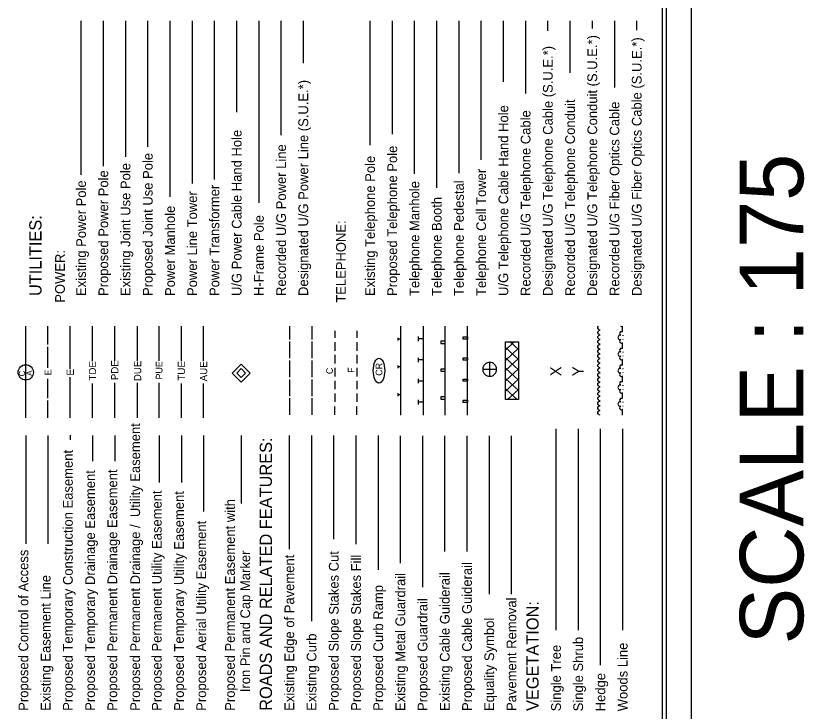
# Model space of a CAD drawing. Extents: x 2026893 to 2039781, y 729195 to 739590.
# Drawn here: x 2037298 to 2039781, y 735661 to 737852 of the extents above; entities that cross this region are included whole.
import ezdxf

# ---------------------------------------------------------------- set-up
doc = ezdxf.new("R2010")
doc.units = 0
for name, color, linetype in [('Prop Easement Permanent Drainage Utility', 7, 'Continuous'), ('Prop ROW Permanent Easement CELL', 7, 'Continuous'), ('Prop WCC CELL', 7, 'Continuous'), ('Scratch_Level_3', 7, 'Continuous'), ('Sheet Cutting Line CELL', 7, 'Continuous'), ('Sheet Plot Border Inside CELL', 7, 'Continuous'), ('Sheet Plot Border Outside CELL', 7, 'Continuous'), ('Sheet Symbology CELL', 7, 'Continuous')]:
    doc.layers.add(name, color=color, linetype=linetype)

msp = doc.modelspace()

# ---------------------------------------------------------------- linework, layer by layer
at = {"layer": 'Prop Easement Permanent Drainage Utility'}
for p, q in [((2037681.1, 736764.7), (2037681.1, 736873.9)), ((2037681.1, 736585.2), (2037681.1, 736694.7))]:
    msp.add_line(p, q, dxfattribs=at)
at = {"layer": 'Prop ROW Permanent Easement CELL'}
msp.add_line((2038007.5, 736725.7), (2038007.5, 736725.7), dxfattribs=at)
for points in [[(2037979.3, 736725.7), (2038007.5, 736753.9), (2038035.6, 736725.7), (2038007.5, 736697.5)], [(2037993.4, 736725.7), (2038007.5, 736739.8), (2038021.5, 736725.7), (2038007.5, 736711.6)]]:
    msp.add_lwpolyline(points, close=True, dxfattribs=at)
at = {"layer": 'Prop WCC CELL'}
msp.add_ellipse((2038441.5, 736733.8), major_axis=(0, 39.2), ratio=0.462467, dxfattribs=at)
at = {"layer": 'Sheet Cutting Line CELL'}
msp.add_line((2039425.3, 733695.9), (2039425.3, 739589.9), dxfattribs=at)
at = {"layer": 'Sheet Plot Border Inside CELL'}
msp.add_lwpolyline([(2039346.7, 733741.4), (2039346.7, 739574.2), (2035653.9, 739574.2), (2035653.9, 733741.4)], close=True, dxfattribs=at)
at = {"layer": 'Sheet Plot Border Outside CELL'}
msp.add_lwpolyline([(2039425.3, 733695.9), (2039425.3, 739589.9), (2035575.3, 739589.9), (2035575.3, 733695.9)], close=True, dxfattribs=at)
at = {"layer": 'Sheet Symbology CELL'}
for p, q in [((2037502.7, 737835.7), (2037502.7, 737350.3)), ((2037572.7, 737835.7), (2037572.7, 737377.5)), ((2037642.7, 737835.7), (2037642.7, 737406.9)), ((2037712.7, 737835.7), (2037712.7, 737438.4)), ((2037782.7, 737835.7), (2037782.7, 737281)), ((2037852.7, 737835.7), (2037852.7, 737323)), ((2037922.7, 737835.7), (2037922.7, 737335.6)), ((2037992.7, 737835.7), (2037992.7, 737547.6)), ((2038062.7, 737835.7), (2038062.7, 737262.1)), ((2038132.7, 737835.7), (2038132.7, 737475.4)), ((2038202.7, 737835.7), (2038202.7, 737702)), ((2038412.7, 737835.7), (2038412.7, 737444.1)), ((2038482.7, 737835.7), (2038482.7, 737478.5)), ((2038552.7, 737835.7), (2038552.7, 737353.2)), ((2038622.7, 737835.7), (2038622.7, 737309)), ((2038692.7, 737835.7), (2038692.7, 737355.7)), ((2038762.7, 737835.7), (2038762.7, 737397.5)), ((2038832.7, 737835.7), (2038832.7, 737643.1)), ((2038902.7, 737835.7), (2038902.7, 737606.3)), ((2038972.7, 737835.7), (2038972.7, 737803.8)), ((2039042.7, 737835.7), (2039042.7, 737671.5)), ((2039112.7, 737835.7), (2039112.7, 737811)), ((2039182.7, 737835.7), (2039182.7, 737625.7)), ((2039252.7, 737835.7), (2039252.7, 737805.8)), ((2037329, 736585.2), (2037329, 736873.9)), ((2037399, 736815.4), (2037399, 736873.9)), ((2037469, 736856.8), (2037469, 736873.9)), ((2037469, 736738.7), (2037469, 736856.8)), ((2037539, 736859.4), (2037539, 736873.9)), ((2037539, 736763.2), (2037539, 736859.4)), ((2037609, 736861), (2037609, 736873.9)), ((2037609, 736764.7), (2037609, 736861)), ((2037749.1, 736861.1), (2037749.1, 736873.9)), ((2037749.1, 736764.9), (2037749.1, 736861.1)), ((2037819.1, 736859.4), (2037819.1, 736873.9)), ((2037819.1, 736763.2), (2037819.1, 736859.4)), ((2037889.1, 736859.4), (2037889.1, 736873.9)), ((2037889.1, 736763.2), (2037889.1, 736859.4)), ((2038160.5, 736831.9), (2038160.5, 736873.9)), ((2038230.5, 736831.9), (2038230.5, 736873.9)), ((2038302.2, 736859.4), (2038302.2, 736837)), ((2038372.2, 736859.4), (2038372.2, 736837)), ((2038510.1, 736593.4), (2038510.1, 736873.4)), ((2038580.1, 736873.4), (2038580.1, 736593.4)), ((2038650.1, 736593.4), (2038650.1, 736873.4)), ((2038720.1, 736593.4), (2038720.1, 736873.4)), ((2039131.2, 736870.4), (2039132.9, 736873.2)), ((2039131.2, 736867.1), (2039131.2, 736870.4)), ((2039132.7, 736864.3), (2039131.2, 736867.1)), ((2039131.2, 736855.5), (2039132.9, 736858.3)), ((2039131.2, 736852.2), (2039131.2, 736855.5)), ((2039135, 736862.2), (2039132.7, 736864.3)), ((2039132.9, 736873.2), (2039133.1, 736873.4)), ((2039132.9, 736858.3), (2039135.2, 736860.3)), ((2039138.3, 736861.1), (2039135, 736862.2)), ((2039135.2, 736860.3), (2039138.2, 736861)), ((2039208.3, 736855.9), (2039208.3, 736873.4)), ((2038501.4, 736828.4), (2038501.4, 736837.1)), ((2038510.1, 736832.7), (2038501.4, 736832.7)), ((2038566.3, 736826.9), (2038566.3, 736840.9)), ((2038580.1, 736833.9), (2038566.3, 736833.9)), ((2039132.7, 736849.4), (2039131.2, 736852.2)), ((2039131.2, 736840.7), (2039132.9, 736843.5)), ((2039131.2, 736837.3), (2039131.2, 736840.7)), ((2039132.7, 736834.5), (2039131.2, 736837.3)), ((2039135, 736847.3), (2039132.7, 736849.4)), ((2039135, 736832.4), (2039132.7, 736834.5)), ((2039132.9, 736843.5), (2039135.2, 736845.4)), ((2039132.9, 736828.6), (2039135.2, 736830.5)), ((2039138.3, 736846.3), (2039135, 736847.3)), ((2039138.3, 736831.4), (2039135, 736832.4)), ((2039135.2, 736845.4), (2039138.2, 736846.1)), ((2039135.2, 736830.5), (2039138.2, 736831.2)), ((2039210.1, 736843.5), (2039210.1, 736845.2)), ((2039210.1, 736831.2), (2039210.1, 736833)), ((2037399, 736742.7), (2037399, 736808.4)), ((2038160.5, 736772.4), (2038160.5, 736824.9)), ((2038230.5, 736772.4), (2038230.5, 736824.9)), ((2038302.2, 736823.4), (2038302.2, 736795.9)), ((2038372.2, 736823.4), (2038372.2, 736795.9)), ((2038839.6, 736642.2), (2038839.6, 736824.6)), ((2038839.6, 736824.6), (2038880.5, 736824.6)), ((2038867.4, 736824.6), (2038839.6, 736798.5)), ((2038880.5, 736768.2), (2038839.6, 736806.5)), ((2038880.5, 736804.6), (2038839.6, 736765.9)), ((2038880.5, 736800.6), (2038855, 736824.6)), ((2038880.5, 736824.6), (2038880.5, 736642.2)), ((2039131.2, 736825.8), (2039132.9, 736828.6)), ((2039131.2, 736822.5), (2039131.2, 736825.8)), ((2039132.7, 736819.7), (2039131.2, 736822.5)), ((2039131.2, 736810.9), (2039132.9, 736813.7)), ((2039131.2, 736807.6), (2039131.2, 736810.9)), ((2039132.7, 736804.8), (2039131.2, 736807.6)), ((2039135, 736817.6), (2039132.7, 736819.7)), ((2039135, 736802.7), (2039132.7, 736804.8)), ((2039132.9, 736813.7), (2039135.2, 736815.6)), ((2039138.3, 736816.5), (2039135, 736817.6)), ((2039135.2, 736815.6), (2039138.2, 736816.3)), ((2039208.3, 736803.4), (2039208.3, 736820.9)), ((2038302.2, 736782.9), (2038302.2, 736755.8)), ((2038372.2, 736782.9), (2038372.2, 736755.8)), ((2039131.2, 736796), (2039132.9, 736798.8)), ((2039131.2, 736792.7), (2039131.2, 736796)), ((2039132.7, 736789.9), (2039131.2, 736792.7)), ((2039131.2, 736781.2), (2039132.9, 736784)), ((2039131.2, 736777.8), (2039131.2, 736781.2)), ((2039135, 736787.8), (2039132.7, 736789.9)), ((2039132.9, 736798.8), (2039135.2, 736800.8)), ((2039132.9, 736784), (2039135.2, 736785.9)), ((2039138.3, 736801.6), (2039135, 736802.7)), ((2039138.3, 736786.8), (2039135, 736787.8)), ((2039135.2, 736800.8), (2039138.2, 736801.5)), ((2039135.2, 736785.9), (2039138.2, 736786.6)), ((2039210.1, 736791), (2039210.1, 736792.7)), ((2039210.1, 736778.7), (2039210.1, 736780.5)), ((2038160.5, 736712.9), (2038160.5, 736765.4)), ((2038230.5, 736712.9), (2038230.5, 736765.4)), ((2038566.3, 736760.4), (2038566.3, 736774.4)), ((2038580.1, 736767.4), (2038566.3, 736767.4)), ((2038790.1, 736737.7), (2038790.1, 736759.5)), ((2038880.5, 736735.7), (2038839.6, 736774.2)), ((2038880.5, 736772.1), (2038839.6, 736733.6)), ((2039132.7, 736775), (2039131.2, 736777.8)), ((2039131.2, 736766.3), (2039132.9, 736769.1)), ((2039131.2, 736763), (2039131.2, 736766.3)), ((2039132.7, 736760.2), (2039131.2, 736763)), ((2039135, 736772.9), (2039132.7, 736775)), ((2039135, 736758.1), (2039132.7, 736760.2)), ((2039132.9, 736769.1), (2039135.2, 736771)), ((2039132.9, 736754.2), (2039135.2, 736756.1)), ((2039138.3, 736771.9), (2039135, 736772.9)), ((2039138.3, 736757), (2039135, 736758.1)), ((2039135.2, 736771), (2039138.2, 736771.7)), ((2039135.2, 736756.1), (2039138.2, 736756.8)), ((2039208.3, 736750.9), (2039208.3, 736768.4)), ((2038302.2, 736742.9), (2038302.2, 736715.6)), ((2038372.2, 736742.9), (2038372.2, 736715.6)), ((2038501.4, 736740.9), (2038501.4, 736749.6)), ((2038510.1, 736745.2), (2038501.4, 736745.2)), ((2038768.3, 736737.7), (2038790.1, 736737.7)), ((2038790.1, 736715.8), (2038790.1, 736737.7)), ((2038790.1, 736737.7), (2038812, 736737.7)), ((2038880.5, 736703.1), (2038839.6, 736741.8)), ((2038880.5, 736739.5), (2038839.6, 736701.2)), ((2039131.2, 736751.4), (2039132.9, 736754.2)), ((2039131.2, 736748.1), (2039131.2, 736751.4)), ((2039132.7, 736745.3), (2039131.2, 736748.1)), ((2039131.2, 736736.5), (2039132.9, 736739.3)), ((2039131.2, 736733.2), (2039131.2, 736736.5)), ((2039132.7, 736730.4), (2039131.2, 736733.2)), ((2039135, 736743.2), (2039132.7, 736745.3)), ((2039135, 736728.3), (2039132.7, 736730.4)), ((2039132.9, 736739.3), (2039135.2, 736741.3)), ((2039138.3, 736742.1), (2039135, 736743.2)), ((2039135.2, 736741.3), (2039138.2, 736742)), ((2039210.1, 736738.5), (2039210.1, 736740.2)), ((2037399, 736646.5), (2037399, 736707.7)), ((2037469, 736594.3), (2037469, 736712.5)), ((2038160.5, 736653.4), (2038160.5, 736705.9)), ((2038230.5, 736653.4), (2038230.5, 736705.9)), ((2038566.3, 736693.9), (2038566.3, 736707.9)), ((2038880.5, 736670.7), (2038839.6, 736709.2)), ((2038880.5, 736707.1), (2038839.6, 736668.6)), ((2039131.2, 736721.7), (2039132.9, 736724.5)), ((2039131.2, 736718.3), (2039131.2, 736721.7)), ((2039132.7, 736715.5), (2039131.2, 736718.3)), ((2039131.2, 736706.8), (2039132.9, 736709.6)), ((2039131.2, 736703.5), (2039131.2, 736706.8)), ((2039135, 736713.4), (2039132.7, 736715.5)), ((2039132.9, 736724.5), (2039135.2, 736726.4)), ((2039132.9, 736709.6), (2039135.2, 736711.5)), ((2039138.3, 736727.3), (2039135, 736728.3)), ((2039138.3, 736712.4), (2039135, 736713.4)), ((2039135.2, 736726.4), (2039138.2, 736727.1)), ((2039135.2, 736711.5), (2039138.2, 736712.2)), ((2039208.3, 736698.4), (2039208.3, 736715.9)), ((2039210.1, 736726.2), (2039210.1, 736728)), ((2037539, 736596.9), (2037539, 736693.2)), ((2037609, 736598.5), (2037609, 736694.7)), ((2037749.1, 736598.6), (2037749.1, 736694.9)), ((2037819.1, 736596.9), (2037819.1, 736693.2)), ((2037889.1, 736596.9), (2037889.1, 736693.2)), ((2038302.2, 736701.7), (2038302.2, 736675.1)), ((2038372.2, 736701.7), (2038372.2, 736675.1)), ((2038580.1, 736700.9), (2038566.3, 736700.9)), ((2039132.7, 736700.7), (2039131.2, 736703.5)), ((2039131.2, 736691.9), (2039132.9, 736694.7)), ((2039131.2, 736688.6), (2039131.2, 736691.9)), ((2039132.7, 736685.8), (2039131.2, 736688.6)), ((2039135, 736698.6), (2039132.7, 736700.7)), ((2039135, 736683.7), (2039132.7, 736685.8)), ((2039132.9, 736694.7), (2039135.2, 736696.6)), ((2039132.9, 736679.8), (2039135.2, 736681.8)), ((2039138.3, 736697.5), (2039135, 736698.6)), ((2039138.3, 736682.6), (2039135, 736683.7)), ((2039135.2, 736696.6), (2039138.2, 736697.3)), ((2039135.2, 736681.8), (2039138.2, 736682.5)), ((2039210.1, 736686), (2039210.1, 736687.7)), ((2038302.2, 736661.5), (2038302.2, 736635.1)), ((2038372.2, 736661.5), (2038372.2, 736635.1)), ((2038501.4, 736653.4), (2038501.4, 736662.1)), ((2038510.1, 736657.7), (2038501.4, 736657.7)), ((2038876.5, 736642.2), (2038839.6, 736676.7)), ((2038880.5, 736674.6), (2038845.9, 736642.2)), ((2039131.2, 736677), (2039132.9, 736679.8)), ((2039131.2, 736673.7), (2039131.2, 736677)), ((2039132.7, 736670.9), (2039131.2, 736673.7)), ((2039131.2, 736662.2), (2039132.9, 736665)), ((2039131.2, 736658.8), (2039131.2, 736662.2)), ((2039132.7, 736656), (2039131.2, 736658.8)), ((2039135, 736668.8), (2039132.7, 736670.9)), ((2039135, 736653.9), (2039132.7, 736656)), ((2039132.9, 736665), (2039135.2, 736666.9)), ((2039138.3, 736667.8), (2039135, 736668.8)), ((2039135.2, 736666.9), (2039138.2, 736667.6)), ((2039208.3, 736645.9), (2039208.3, 736663.4)), ((2039210.1, 736673.7), (2039210.1, 736675.5)), ((2037399, 736585.2), (2037399, 736639.5)), ((2038160.5, 736593.9), (2038160.5, 736646.4)), ((2038230.5, 736593.9), (2038230.5, 736646.4)), ((2038566.3, 736627.4), (2038566.3, 736641.4)), ((2038580.1, 736634.4), (2038566.3, 736634.4)), ((2038841.7, 736642.2), (2038839.6, 736644.1)), ((2038880.5, 736642.2), (2038839.6, 736642.2)), ((2039131.2, 736647.3), (2039132.9, 736650.1)), ((2039131.2, 736644), (2039131.2, 736647.3)), ((2039132.7, 736641.2), (2039131.2, 736644)), ((2039131.2, 736632.4), (2039132.9, 736635.2)), ((2039131.2, 736629.1), (2039131.2, 736632.4)), ((2039135, 736639.1), (2039132.7, 736641.2)), ((2039132.9, 736650.1), (2039135.2, 736652)), ((2039132.9, 736635.2), (2039135.2, 736637.1)), ((2039138.3, 736652.9), (2039135, 736653.9)), ((2039138.3, 736638), (2039135, 736639.1)), ((2039135.2, 736652), (2039138.2, 736652.7)), ((2039135.2, 736637.1), (2039138.2, 736637.8)), ((2039210.1, 736633.5), (2039210.1, 736635.2)), ((2038302.2, 736593.9), (2038302.2, 736620.5)), ((2038372.2, 736593.9), (2038372.2, 736620.5)), ((2039132.7, 736626.3), (2039131.2, 736629.1)), ((2039131.2, 736617.5), (2039132.9, 736620.3)), ((2039131.2, 736614.2), (2039131.2, 736617.5)), ((2039132.7, 736611.4), (2039131.2, 736614.2)), ((2039131.2, 736602.7), (2039132.9, 736605.5)), ((2039135, 736624.2), (2039132.7, 736626.3)), ((2039135, 736609.3), (2039132.7, 736611.4)), ((2039132.9, 736620.3), (2039135.2, 736622.3)), ((2039132.9, 736605.5), (2039135.2, 736607.4)), ((2039138.3, 736623.1), (2039135, 736624.2)), ((2039138.3, 736608.3), (2039135, 736609.3)), ((2039135.2, 736622.3), (2039138.2, 736623)), ((2039135.2, 736607.4), (2039138.2, 736608.1)), ((2039208.3, 736593.4), (2039208.3, 736610.9)), ((2039210.1, 736621.2), (2039210.1, 736623)), ((2037469, 736585.2), (2037469, 736594.3)), ((2037539, 736585.2), (2037539, 736596.9)), ((2037609, 736585.2), (2037609, 736598.5)), ((2037749.1, 736585.2), (2037749.1, 736598.6)), ((2037819.1, 736585.2), (2037819.1, 736596.9)), ((2037889.1, 736585.2), (2037889.1, 736596.9)), ((2039131.2, 736599.3), (2039131.2, 736602.7)), ((2039132.7, 736596.5), (2039131.2, 736599.3)), ((2039135, 736594.4), (2039132.7, 736596.5)), ((2039138.3, 736593.4), (2039135, 736594.4)), ((2038998.3, 736550), (2038998.3, 735916.1)), ((2039068.3, 736550), (2039068.3, 735916.1)), ((2039138.3, 736550), (2039138.3, 735805.6)), ((2039208.3, 736550), (2039208.3, 735916.1)), ((2037329, 736529.1), (2037329, 736187.7)), ((2037399, 736529.1), (2037399, 736187.7)), ((2037469, 736530.4), (2037469, 736515.8)), ((2037539, 736529.1), (2037539, 736448.1)), ((2037609, 736529.1), (2037609, 736448.1)), ((2037749.1, 736529.1), (2037749.1, 736381.6)), ((2037819.1, 736529.1), (2037819.1, 736381.6)), ((2037889.1, 736529.1), (2037889.1, 736289.5)), ((2038007.5, 736529.1), (2038007.5, 736315.5)), ((2038158.5, 736529.1), (2038158.5, 736170.9)), ((2038228.5, 736529.1), (2038228.5, 735944.1)), ((2038298.5, 736529.1), (2038298.5, 736202.9)), ((2038368.5, 736529.1), (2038368.5, 736187)), ((2038438.5, 736529.1), (2038438.5, 736105.8)), ((2038508.1, 736528.5), (2038508.1, 736126.6)), ((2038578.1, 736528.5), (2038578.1, 736051.7)), ((2038648.1, 736528.5), (2038648.1, 736163.5)), ((2038718.1, 736528.5), (2038718.1, 736163.5)), ((2038788.1, 736528.5), (2038788.1, 736029.3)), ((2038858.1, 736528.5), (2038858.1, 736029.3))]:
    msp.add_line(p, q, dxfattribs=at)
for points in [[(2035662.8, 739530.4), (2035662.8, 734280.4), (2039334.3, 734280.4), (2039334.3, 739530.4)], [(2038706.1, 736833), (2038706.1, 736840), (2038720.1, 736840), (2038720.1, 736833)], [(2038650.1, 736819), (2038650.1, 736826), (2038636.1, 736826), (2038636.1, 736819)], [(2038706.1, 736766.5), (2038706.1, 736773.5), (2038720.1, 736773.5), (2038720.1, 736766.5)], [(2038650.1, 736731.5), (2038650.1, 736738.5), (2038636.1, 736738.5), (2038636.1, 736731.5)], [(2038706.1, 736700), (2038706.1, 736707), (2038720.1, 736707), (2038720.1, 736700)], [(2038650.1, 736644), (2038650.1, 736651), (2038636.1, 736651), (2038636.1, 736644)], [(2038706.1, 736633.5), (2038706.1, 736640.5), (2038720.1, 736640.5), (2038720.1, 736633.5)]]:
    msp.add_lwpolyline(points, close=True, dxfattribs=at)
msp.add_circle((2037329, 736728.2), 24.1, dxfattribs=at)
for centre, radius, start, end in [((2039204.8, 736850.5), 5.53, 50.7685, 251.5651), ((2039204.8, 736878.5), 5.53, 246.251, 293.749), ((2039201.3, 736838.2), 7.22, 75.9638, 284.0362), ((2039204.8, 736826), 5.53, 108.435, 309.2315), ((2039201.3, 736785.7), 7.22, 75.9638, 284.0362), ((2039204.8, 736798), 5.53, 50.7685, 251.5651), ((2038790.2, 736737.7), 21.9, 89.9944, 179.9989), ((2038790.2, 736737.7), 21.9, 359.9944, 89.9989), ((2039204.8, 736773.5), 5.53, 108.435, 309.2315), ((2038790.2, 736737.7), 21.9, 179.9944, 269.9989), ((2038790.2, 736737.7), 21.9, 269.9944, 359.9989), ((2039201.3, 736733.2), 7.22, 75.9638, 284.0362), ((2039204.8, 736745.5), 5.53, 50.7685, 251.5651), ((2039204.8, 736721), 5.53, 108.435, 309.2315), ((2039201.3, 736680.7), 7.22, 75.9638, 284.0362), ((2039204.8, 736693), 5.53, 50.7685, 251.5651), ((2039204.8, 736668.5), 5.53, 108.435, 309.2315), ((2039201.3, 736628.2), 7.22, 75.9638, 284.0362), ((2039204.8, 736640.5), 5.53, 50.7685, 251.5651), ((2039204.8, 736616), 5.53, 108.435, 309.2315)]:
    msp.add_arc(centre, radius, start, end, dxfattribs=at)

# ---------------------------------------------------------------- texts
at = {"layer": 'Prop Easement Permanent Drainage Utility'}
msp.add_text('DUE', height=22.92, rotation=90, dxfattribs=at).set_placement((2037692.6, 736700.3))
at = {"layer": 'Prop WCC CELL'}
msp.add_text('CR', height=21, rotation=90, dxfattribs=at).set_placement((2038451.9, 736717.3))
at = {"layer": 'Scratch_Level_3'}
msp.add_text(' SCALE : 175', height=200, rotation=90, dxfattribs=at).set_placement((2039777.9, 735796.6))
at = {"layer": 'Sheet Symbology CELL'}
for s, height, p in [('Designated U/G Telephone Conduit (S.U.E.*)', 30.625, (2039128.6, 736968.8)), ('Designated U/G Fiber Optics Cable (S.U.E.*)', 30.625, (2039268.6, 736968.8)), ('Designated U/G Telephone Cable (S.U.E.*)', 30.625, (2038988.6, 736968.8)), ('Designated U/G Power Line (S.U.E.*)', 30.625, (2038218.5, 736968.8)), ('Recorded U/G Telephone Conduit', 30.625, (2039058.6, 736968.8)), ('Recorded U/G Fiber Optics Cable', 30.625, (2039198.6, 736968.8)), ('U/G Telephone Cable Hand Hole', 30.625, (2038848.6, 736968.8)), ('Recorded U/G Telephone Cable', 30.625, (2038918.6, 736968.8)), ('U/G Power Cable Hand Hole', 30.625, (2038008.6, 736968.7)), ('Recorded U/G Power Line', 30.625, (2038148.6, 736968.7)), ('Proposed Telephone Pole', 30.625, (2038498.6, 736968.7)), ('Proposed Joint Use Pole', 30.625, (2037728.6, 736968.7)), ('Existing Telephone Pole', 30.625, (2038428.6, 736968.7)), ('Existing Joint Use Pole', 30.625, (2037658.5, 736968.7)), ('Proposed Power Pole', 30.625, (2037588.6, 736968.7)), ('Telephone Cell Tower', 30.625, (2038778.6, 736968.8)), ('Existing Power Pole', 30.625, (2037518.6, 736968.7)), ('Telephone Manhole', 30.625, (2038568.6, 736968.7)), ('Telephone Pedestal', 30.625, (2038708.6, 736968.7)), ('Power Transformer', 30.625, (2037938.5, 736968.7)), ('Power Line Tower', 30.625, (2037868.5, 736968.7)), ('Telephone Booth', 30.625, (2038638.6, 736968.7)), ('Power Manhole', 30.625, (2037798.6, 736968.7)), ('UTILITIES:', 38.5, (2037378.6, 736968.6)), ('H-Frame Pole', 30.625, (2038078.6, 736968.7)), ('TELEPHONE:', 30.63, (2038337, 736947.5)), ('POWER:', 30.63, (2037452.1, 736947.5)), ('TDE', 22.92, (2037550.6, 736702.3)), ('PDE', 22.92, (2037620.6, 736703.5)), ('PUE', 21, (2037759.6, 736705.7)), ('TUE', 22.92, (2037830.6, 736702.2)), ('AUE', 22.92, (2037900.6, 736699.9)), ('C', 18.9, (2037326.2, 736715.4)), ('A', 18.9, (2037348.9, 736717.3)), ('E', 21, (2037409.5, 736718.9)), ('E', 22.9, (2037480.6, 736718.1)), ('C', 20.7, (2038296.1, 736722.7)), ('F', 20.7, (2038363.9, 736726.9)), ('X', 35, (2039015.8, 736715.9)), ('Y', 35, (2039085.8, 736715.9)), ('Proposed Permanent Drainage /  Utility Easement', 30.625, (2037689, 735662)), ('ROADS AND RELATED FEATURES:', 38.5, (2038104.4, 735662)), ('Proposed Temporary Construction Easement', 30.625, (2037477, 735662)), ('Proposed Temporary Drainage Easement', 30.625, (2037547, 735662)), ('Proposed Permanent Drainage Easement', 30.625, (2037617, 735662)), ('Proposed Permanent Utility Easement', 30.625, (2037757, 735662)), ('Proposed Temporary Utility Easement', 30.625, (2037827, 735662)), ('Proposed Permanent Easement with', 30.625, (2037987.5, 735662)), ('Proposed Aerial Utility Easement', 30.625, (2037897, 735662)), ('Proposed Control of Access', 30.625, (2037337, 735662)), ('Iron Pin and Cap Marker', 30.625, (2038035.6, 735720.6)), ('Proposed Slope Stakes Cut', 30.625, (2038314.4, 735662)), ('Existing Edge of Pavement', 30.625, (2038174.4, 735662)), ('Proposed Slope Stakes Fill', 30.625, (2038384.4, 735662)), ('Proposed Cable Guiderail', 30.625, (2038734, 735661.5)), ('Existing Easement Line', 30.625, (2037407, 735662)), ('Existing Metal Guardrail', 30.625, (2038524, 735661.4)), ('Existing Cable Guiderail', 30.625, (2038664, 735661.5)), ('Proposed Curb Ramp', 30.625, (2038454.4, 735662)), ('Proposed Guardrail', 30.625, (2038594, 735661.5)), ('Pavement Removal', 30.625, (2038874, 735661.5)), ('VEGETATION:', 38.5, (2038944.3, 735661.4)), ('Equality Symbol', 30.625, (2038804, 735661.5)), ('Existing Curb', 30.625, (2038244.4, 735662)), ('Single Shrub', 30.625, (2039084.2, 735660.4)), ('Single Tree', 30.625, (2039014.2, 735660.4)), ('Woods Line', 30.63, (2039224.2, 735660.4)), ('Hedge', 30.63, (2039154.2, 735660.4))]:
    msp.add_text(s, height=height, rotation=90, dxfattribs=at).set_placement(p)

doc.saveas('drawing.dxf')
